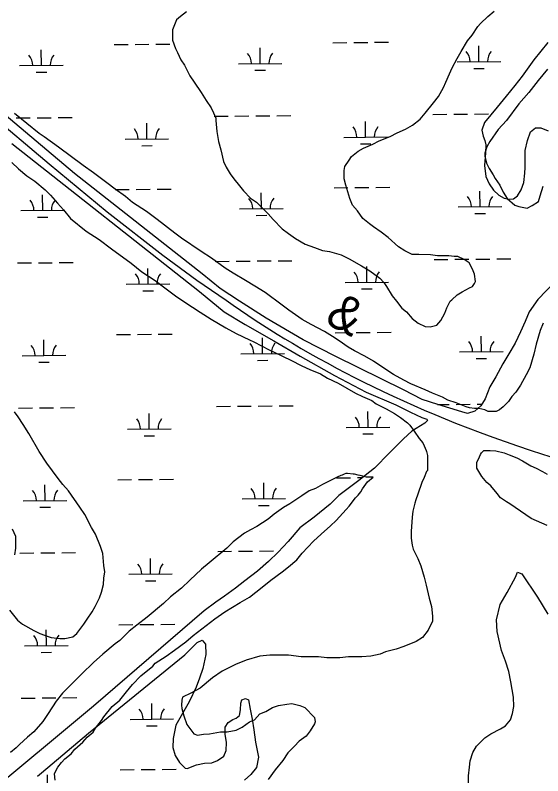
# Model space of a CAD drawing. Extents: x 3568792 to 3606828, y 529143 to 554785.
# Drawn here: x 3581727 to 3582938, y 542432 to 544177 of the extents above; entities that cross this region are included whole.
import ezdxf

# ---------------------------------------------------------------- set-up
doc = ezdxf.new("R2010")
doc.units = 0
for name, color, linetype in [('V-RAIL-IDEN', 7, 'Continuous'), ('V-RAIL-TRAK', 7, 'Continuous'), ('V-SITE-VEGE', 7, 'Continuous'), ('V-WETL-SWMP', 7, 'Continuous')]:
    doc.layers.add(name, color=color, linetype=linetype)

msp = doc.modelspace()

# ---------------------------------------------------------------- linework, layer by layer
at = {"layer": 'V-RAIL-TRAK'}
for points in [[(3580851.8, 544633.4), (3580996.5, 544512.4), (3581029.1, 544485.4), (3581051.8, 544466.2), (3581134, 544398.3), (3581292.9, 544265), (3581431.3, 544149.1), (3581532, 544064.7), (3581661.7, 543956.6), (3581805.1, 543836.1), (3581938.4, 543725.6), (3582066.2, 543626.6), (3582144.1, 543569.4), (3582211.4, 543523.5)], [(3582211.4, 543523.5), (3582227.8, 543511.8), (3582244.3, 543500.2), (3582260.9, 543488.8), (3582277.7, 543477.6), (3582294.6, 543466.6), (3582311.6, 543455.8), (3582328.8, 543445.2), (3582346, 543434.7), (3582363.4, 543424.5), (3582383.5, 543412.7), (3582403.7, 543401.2), (3582424, 543389.8), (3582444.5, 543378.6), (3582465, 543367.5), (3582485.6, 543356.7), (3582506.3, 543346.1), (3582527.1, 543335.6), (3582548, 543325.3), (3582571.4, 543314.1), (3582595, 543303.1), (3582618.6, 543292.3), (3582642.3, 543281.7), (3582666.1, 543271.2), (3582690, 543260.9), (3582713.9, 543250.9), (3582737.9, 543241), (3582766.2, 543230.2), (3582794.6, 543219.6), (3582823, 543209.2), (3582851.5, 543199.1), (3582880.1, 543189.2), (3582908.8, 543179.4), (3582937.5, 543169.9), (3582966.3, 543160.6)]]:
    msp.add_lwpolyline(points, dxfattribs=at)
at = {"layer": 'V-SITE-VEGE'}
for points in [[(3582120.1, 544184.3), (3582106.6, 544174.1), (3582097.5, 544166.1), (3582088.4, 544143.5), (3582088.4, 544119.7), (3582095.2, 544100.5), (3582099.7, 544091.4), (3582107.7, 544074.4), (3582115.6, 544062), (3582128, 544038.2), (3582138.2, 544023.5), (3582154.1, 543999.7), (3582165.4, 543981.6)], [(3582794.9, 544158.1), (3582811.9, 544174), (3582826.7, 544186.4)], [(3582165.4, 543981.6), (3582176.7, 543964.6), (3582182.4, 543953.3), (3582188, 543940.8), (3582188, 543935.2), (3582190.3, 543910.2), (3582193.7, 543887.6), (3582199.4, 543868.4), (3582205, 543841.2), (3582211.8, 543828.7), (3582220.9, 543812.9), (3582228.8, 543801.5), (3582242.4, 543785.7), (3582251.4, 543774.4), (3582267.3, 543757.4), (3582280.9, 543748.3), (3582308, 543721.1), (3582319.4, 543708.7), (3582339.7, 543687.2), (3582354.4, 543675.9), (3582370.3, 543664.5), (3582392.9, 543652.1), (3582414.5, 543644.1), (3582432.6, 543637.3), (3582448.4, 543635.1), (3582475.6, 543627.2), (3582493.7, 543618.1), (3582522, 543602.2), (3582541.3, 543590.9), (3582563.9, 543573.9), (3582573, 543563.7), (3582579.7, 543554.7), (3582592.2, 543533.2), (3582602.4, 543520.7), (3582614.8, 543504.9), (3582625, 543496.9), (3582638.6, 543481.1), (3582652.2, 543470.9), (3582668, 543463), (3582679.4, 543461.8), (3582695.2, 543466.3), (3582704.3, 543476.5), (3582713.3, 543493.5), (3582717.9, 543506), (3582725.8, 543520.7), (3582729.2, 543524.1), (3582741.7, 543535.4), (3582753, 543542.2), (3582770, 543551.3), (3582776.8, 543554.7), (3582781.3, 543561.4), (3582783.5, 543566), (3582781.3, 543583), (3582776.8, 543594.3), (3582768.8, 543609), (3582757.5, 543616.9), (3582742.8, 543623.7), (3582734.9, 543623.7), (3582722.4, 543624.9), (3582696.4, 543624.9), (3582680.5, 543627.1), (3582653.3, 543628.3), (3582638.6, 543628.3), (3582621.6, 543636.2), (3582606.9, 543645.3), (3582583.2, 543666.8), (3582567.3, 543679.2), (3582549.2, 543691.7), (3582540.1, 543698.5), (3582525.4, 543710.9), (3582513, 543727.9), (3582501.6, 543741.5), (3582494.9, 543756.2), (3582485.8, 543786.8), (3582482.4, 543801.5), (3582482.4, 543820.8), (3582483.5, 543829.8), (3582493.7, 543844.5), (3582499.4, 543852.5), (3582514.1, 543864.9), (3582526.6, 543871.7), (3582548.1, 543880.8), (3582562.8, 543888.7), (3582587.7, 543898.9), (3582603.6, 543906.8), (3582622.8, 543915.9), (3582638.7, 543924.9), (3582656.8, 543938.5), (3582668.1, 543952.1), (3582687.4, 543975.9), (3582698.7, 543990.6), (3582710, 544010.9), (3582715.7, 544023.4), (3582723.6, 544042.7), (3582730.4, 544056.2), (3582741.7, 544077.7), (3582750.8, 544093.6), (3582765.5, 544118.5), (3582775.7, 544131), (3582789.3, 544151.3), (3582794.9, 544158.1)], [(3582948.9, 544052.8), (3582927.4, 544026.8), (3582905.9, 543999.6), (3582883.2, 543973.6), (3582854.9, 543935.1), (3582835.7, 543914.7), (3582816.4, 543887.5), (3582809.6, 543875.1), (3582805.1, 543860.4), (3582805.1, 543853.6), (3582808.5, 543837.7), (3582815.3, 543825.2), (3582824.3, 543810.5), (3582828.9, 543802.6), (3582839.1, 543786.8), (3582847, 543770.9), (3582856, 543756.2), (3582874.1, 543741.5), (3582883.2, 543738.1), (3582902.5, 543734.7), (3582913.8, 543740.3), (3582928.5, 543749.4), (3582931.9, 543763), (3582938.7, 543784.5)], [(3582781.2, 543275), (3582769.9, 543276.1), (3582762, 543278.4), (3582739.4, 543287.5), (3582720.1, 543294.2), (3582707.7, 543301), (3582685, 543310.1), (3582668, 543318), (3582635.2, 543331.6), (3582619.3, 543339.6), (3582595.6, 543353.1), (3582577.5, 543364.5), (3582549.2, 543383.7), (3582529.9, 543395), (3582506.1, 543407.5), (3582491.4, 543415.4), (3582471, 543430.1), (3582455.2, 543440.3), (3582437.1, 543451.7), (3582406.5, 543467.5), (3582386.1, 543478.8), (3582355.6, 543500.4), (3582339.7, 543511.7), (3582301.2, 543541.1), (3582277.4, 543555.8), (3582255.9, 543568.3), (3582227.6, 543585.3), (3582209.5, 543596.6), (3582177.8, 543619.3), (3582154, 543635.1), (3582108.8, 543665.7), (3582094, 543677), (3582053.3, 543708.7), (3582028.4, 543726.8), (3581996.7, 543747.2), (3581980.8, 543760.8), (3581957.1, 543777.8), (3581937.8, 543792.5), (3581907.2, 543815.2), (3581883.5, 543832.2), (3581826.9, 543874.1), (3581794, 543897.8), (3581782.7, 543905.8), (3581726.1, 543951.1)], [(3581719.3, 543839), (3581735.1, 543824.3), (3581754.4, 543808.4), (3581772.5, 543795.9), (3581796.3, 543776.7), (3581808.7, 543764.2), (3581824.6, 543746.1), (3581838.2, 543730.3), (3581854, 543711), (3581890.2, 543681.6), (3581919.7, 543662.3), (3581948, 543640.8), (3581993.3, 543608), (3582018.2, 543588.7), (3582048.7, 543568.3), (3582068, 543553.6), (3582095.1, 543533.2), (3582116.7, 543518.5), (3582151.8, 543495.9), (3582176.7, 543480), (3582210.6, 543459.6), (3582234.4, 543447.2), (3582265, 543432.4), (3582275.2, 543427.9), (3582310.3, 543409.8), (3582318.2, 543405.3), (3582342, 543393.9), (3582360.1, 543386), (3582385, 543372.4), (3582403.1, 543364.5), (3582428, 543354.3), (3582443.9, 543344.1), (3582468.8, 543332.8), (3582508.4, 543310.1), (3582524.2, 543302.2), (3582545.7, 543293.1), (3582555.9, 543285.2), (3582578.6, 543273.9), (3582597.8, 543263.7), (3582611.4, 543254.6), (3582627.3, 543242.2), (3582632.9, 543236.5), (3582643.1, 543222.9), (3582654.4, 543205.9), (3582662.4, 543195.8), (3582665.8, 543189), (3582670.3, 543178.8), (3582671.4, 543176.5), (3582673.7, 543167.4), (3582673.7, 543132.3), (3582671.4, 543130.1), (3582665.7, 543116.5), (3582660.1, 543105.2), (3582651, 543078), (3582646.5, 543065.5), (3582644.2, 543057.6), (3582639.7, 543039.5), (3582638.6, 543025.9), (3582636.3, 542993.1), (3582636.3, 542977.2), (3582638.5, 542961.4), (3582640.8, 542952.3), (3582651, 542930.8), (3582657.8, 542913.8), (3582665.7, 542887.8), (3582670.2, 542869.7), (3582677, 542840.2), (3582682.7, 542821), (3582685, 542798.3), (3582684.9, 542787), (3582674.8, 542766.6), (3582662.3, 542749.7), (3582647.6, 542740.6), (3582619.3, 542729.3), (3582601.2, 542722.5), (3582577.4, 542716.8), (3582564.9, 542711.2), (3582543.4, 542706.6), (3582523, 542705.5), (3582492.5, 542705.5), (3582472.1, 542703.3)], [(3582938.6, 543470.8), (3582931.9, 543453.9), (3582922.8, 543422.2), (3582917.1, 543399.5), (3582908.1, 543367.8), (3582900.1, 543352), (3582886.6, 543328.2), (3582876.4, 543312.3), (3582867.3, 543302.2), (3582859.4, 543290.8), (3582846.9, 543278.4), (3582839, 543271.6), (3582831.1, 543268.2), (3582813, 543268.2), (3582805, 543271.6), (3582791.4, 543275), (3582781.2, 543275)], [(3581714.6, 542812), (3581732.7, 542789.4), (3581744.1, 542780.3), (3581770.1, 542765.6), (3581783.7, 542758.8), (3581805.2, 542750.9), (3581809.7, 542749.8), (3581830.1, 542747.5), (3581841.4, 542747.5), (3581859.6, 542750.9), (3581868.6, 542758.8), (3581884.5, 542780.3), (3581892.4, 542791.6), (3581903.7, 542808.6), (3581910.5, 542821.1), (3581920.7, 542840.3), (3581925.2, 542853.9), (3581929.8, 542870.9), (3581930.9, 542885.6), (3581933.2, 542900.3), (3581930.9, 542915.1), (3581928.6, 542942.2), (3581923, 542958.1), (3581911.7, 542986.4), (3581902.6, 543002.2), (3581886.8, 543031.7), (3581875.4, 543048.7), (3581849.4, 543086), (3581837, 543100.7), (3581825.6, 543114.3), (3581799.6, 543149.4), (3581782.6, 543176.6), (3581758.8, 543217.4), (3581745.3, 543237.8), (3581733.9, 543255.9), (3581726, 543267.2)], [(3582947.7, 543006.6), (3582911.4, 543022.5), (3582886.5, 543039.5), (3582862.7, 543056.5), (3582854.8, 543061), (3582841.2, 543070.1), (3582833.3, 543080.2), (3582818.6, 543097.2), (3582809.5, 543105.2), (3582798.2, 543118.7), (3582793.7, 543126.7), (3582786.9, 543138), (3582786.9, 543151.6), (3582790.3, 543158.4), (3582794.8, 543169.7), (3582797.1, 543173.1), (3582802.7, 543178.8), (3582817.5, 543178.7), (3582829.9, 543177.6), (3582849.2, 543173.1), (3582860.5, 543168.6), (3582878.6, 543161.8), (3582891.1, 543155), (3582910.3, 543143.6), (3582922.8, 543138), (3582937.5, 543130.1), (3582947.7, 543124.4)], [(3582339.6, 542900.3), (3582354.4, 542911.6), (3582373.6, 542927.4), (3582386.1, 542943.3), (3582412.1, 542970.5), (3582429.1, 542986.3), (3582450.6, 543005.6), (3582464.2, 543018), (3582486.8, 543042.9), (3582493.6, 543050.8), (3582508.4, 543070.1), (3582514, 543075.8), (3582520.8, 543083.7), (3582524.2, 543090.5), (3582535.5, 543106.3), (3582549.1, 543117.6), (3582533.3, 543117.6), (3582518.6, 543121), (3582514, 543122.2), (3582506.1, 543124.4), (3582502.7, 543124.4), (3582490.2, 543125.6), (3582485.7, 543125.6), (3582482.3, 543124.4), (3582477.8, 543122.2), (3582474.4, 543121), (3582466.5, 543117.7), (3582445, 543106.3), (3582432.5, 543100.7), (3582416.6, 543091.6), (3582401.9, 543086), (3582384.9, 543074.6), (3582373.6, 543066.7), (3582357.8, 543056.5), (3582343, 543047.5), (3582321.5, 543032.8), (3582307.9, 543021.4), (3582281.9, 543004.5), (3582267.2, 542996.5), (3582253.6, 542988.6), (3582227.6, 542969.4), (3582212.8, 542954.6), (3582172.1, 542920.7), (3582155.1, 542906), (3582127.9, 542881.1), (3582108.7, 542862.9), (3582083.7, 542842.6), (3582067.9, 542827.9), (3582030.5, 542796.2), (3582006.7, 542778), (3581988.6, 542764.5), (3581967.1, 542742.9), (3581956.9, 542735), (3581928.6, 542711.2), (3581907.1, 542692), (3581879.9, 542666), (3581835.8, 542621.8), (3581821, 542603.7), (3581802.9, 542575.4), (3581790.5, 542557.3), (3581770.1, 542533.5), (3581755.4, 542521.1), (3581737.2, 542504.1), (3581729.3, 542496.2), (3581716.9, 542486)], [(3581720.3, 542998.9), (3581728.2, 542981.9), (3581728.2, 542954.7), (3581726, 542938.9)], [(3581818.8, 542422.5), (3581817.6, 542437.3), (3581821, 542445.2), (3581825.5, 542452), (3581833.5, 542463.3), (3581841.4, 542471.2), (3581856.1, 542482.6), (3581864, 542493.9), (3581882.2, 542509.7), (3581892.4, 542521), (3581905.9, 542532.4), (3581911.6, 542541.4), (3581925.2, 542559.5), (3581930.9, 542567.5), (3581950.1, 542591.2), (3581967.1, 542605.9), (3581982.9, 542625.2), (3581996.5, 542642.2), (3582015.8, 542661.4), (3582043, 542684.1), (3582048.6, 542690.9), (3582073.5, 542706.7), (3582092.8, 542720.3), (3582118.8, 542739.5), (3582135.8, 542754.2), (3582165.3, 542776.9), (3582185.6, 542792.7), (3582208.3, 542808.6), (3582243.4, 542830.1), (3582264.9, 542842.5), (3582294.3, 542865.2), (3582313.6, 542881), (3582339.6, 542900.3)], [(3582767.6, 542396.4), (3582767.6, 542432.6), (3582769.8, 542451.9), (3582771, 542466.6), (3582777.8, 542485.8), (3582785.7, 542500.6), (3582804.9, 542519.8), (3582818.5, 542528.9), (3582841.2, 542540.2), (3582852.5, 542547), (3582863.8, 542560.5), (3582868.3, 542575.3), (3582871.7, 542591.1), (3582870.6, 542612.6), (3582865, 542647.7), (3582860.4, 542671.5), (3582852.5, 542695.3), (3582843.5, 542720.2), (3582833.3, 542763.2), (3582832.1, 542790.4), (3582840.1, 542825.5), (3582855.9, 542852.7), (3582875.2, 542887.8), (3582879.7, 542899.1), (3582889.9, 542895.7), (3582926.1, 542842.5), (3582949.9, 542802.8)], [(3582472.1, 542703.3), (3582442.6, 542703.3), (3582423.4, 542705.5), (3582383.8, 542705.5), (3582354.3, 542708.9), (3582311.3, 542708.9), (3582288.7, 542706.7), (3582257, 542697.6), (3582233.2, 542687.4), (3582202.6, 542672.7), (3582180, 542656.9), (3582151.7, 542633.1), (3582130.1, 542621.8), (3582110.9, 542612.7), (3582109.8, 542605.9), (3582108.6, 542594.6), (3582109.8, 542586.7), (3582114.3, 542569.7), (3582121.1, 542550.4), (3582136.9, 542528.9), (3582146, 542525.5), (3582159.6, 542527.8), (3582173.2, 542528.9), (3582198.1, 542533.5), (3582213.9, 542533.5), (3582234.3, 542536.8), (3582247.9, 542543.6), (3582264.9, 542556.1), (3582276.2, 542560.6), (3582288.6, 542574.2), (3582302.2, 542579.9), (3582318.1, 542588.9), (3582331.7, 542593.4), (3582350.9, 542596.8), (3582362.2, 542598), (3582380.4, 542593.4), (3582391.7, 542588.9), (3582414.3, 542566.3), (3582415.5, 542556.1), (3582414.3, 542551.5), (3582404.1, 542535.7), (3582395.1, 542523.2), (3582379.2, 542511.9), (3582367.9, 542500.6), (3582353.2, 542484.8), (3582341.8, 542467.8), (3582323.7, 542446.3), (3582307.9, 542423.6)]]:
    msp.add_lwpolyline(points, dxfattribs=at)
at = {"layer": 'V-WETL-SWMP'}
for p, q in [((3581954.3, 544109.7), (3581986.3, 544109.9)), ((3582002.3, 544110.1), (3582034.3, 544110.3)), ((3582050.3, 544110.5), (3582082.3, 544110.7)), ((3582456.2, 544113.9), (3582488.2, 544114.2)), ((3582504.2, 544114.3), (3582536.2, 544114.6)), ((3582552.2, 544114.7), (3582584.2, 544115)), ((3581787.6, 544061.8), (3581787.3, 544097.8)), ((3582289.5, 544066), (3582289.2, 544102)), ((3582791.4, 544070.3), (3582791.1, 544106.3)), ((3581737.6, 544061.4), (3581837.6, 544062.2)), ((3582239.5, 544065.6), (3582339.5, 544066.5)), ((3582741.4, 544069.9), (3582841.4, 544070.7)), ((3581775.7, 544046.3), (3581799.7, 544046.5)), ((3582277.6, 544050.5), (3582301.6, 544050.7)), ((3582779.5, 544054.8), (3582803.5, 544055)), ((3581729.8, 543941.3), (3581761.8, 543941.5)), ((3581777.8, 543941.7), (3581809.8, 543941.9)), ((3581825.8, 543942.1), (3581857.8, 543942.3)), ((3582183.7, 543945.1), (3582215.7, 543945.3)), ((3582231.7, 543945.5), (3582263.7, 543945.8)), ((3582279.7, 543945.9), (3582311.7, 543946.2)), ((3582327.7, 543946.3), (3582359.7, 543946.6)), ((3582685.6, 543949.3), (3582717.6, 543949.6)), ((3582733.6, 543949.7), (3582765.6, 543950)), ((3582781.6, 543950.1), (3582813.6, 543950.4)), ((3582029.5, 543893), (3582029.2, 543929)), ((3582531.4, 543897.3), (3582531.1, 543933.3)), ((3581979.5, 543892.6), (3582079.5, 543893.5)), ((3582481.4, 543896.8), (3582581.4, 543897.7)), ((3582017.6, 543877.5), (3582041.6, 543877.7)), ((3582519.5, 543881.7), (3582543.5, 543881.9)), ((3582005.1, 543777.4), (3582037.1, 543777.7)), ((3582053.1, 543777.8), (3582085.1, 543778.1)), ((3582459, 543781.2), (3582491, 543781.5)), ((3582507, 543781.6), (3582539, 543781.9)), ((3582555, 543782), (3582587, 543782.3)), ((3581790.4, 543729.1), (3581790.1, 543765.1)), ((3581957.1, 543777), (3581989.1, 543777.3)), ((3582292.3, 543733.4), (3582292, 543769.4)), ((3582794.2, 543737.6), (3582793.9, 543773.6)), ((3581740.4, 543728.7), (3581840.4, 543729.5)), ((3582242.3, 543733), (3582342.3, 543733.8)), ((3582744.2, 543737.2), (3582844.2, 543738)), ((3581778.5, 543713.6), (3581802.5, 543713.8)), ((3582280.4, 543717.9), (3582304.4, 543718.1)), ((3582782.3, 543722.1), (3582806.3, 543722.3)), ((3581732.5, 543608.6), (3581764.5, 543608.8)), ((3581780.5, 543609), (3581812.5, 543609.2)), ((3581828.5, 543609.4), (3581860.5, 543609.6)), ((3582186.5, 543612.4), (3582218.5, 543612.7)), ((3582234.5, 543612.8), (3582266.5, 543613.1)), ((3582282.5, 543613.2), (3582314.5, 543613.5)), ((3582330.5, 543613.6), (3582362.5, 543613.9)), ((3582688.4, 543616.7), (3582720.4, 543616.9)), ((3582736.4, 543617.1), (3582768.4, 543617.3)), ((3582784.4, 543617.5), (3582816.4, 543617.7)), ((3582832.4, 543617.9), (3582864.4, 543618.1)), ((3582032.3, 543560.3), (3582032, 543596.3)), ((3582534.2, 543564.6), (3582533.9, 543600.6)), ((3581982.3, 543559.9), (3582082.3, 543560.8)), ((3582484.2, 543564.2), (3582584.2, 543565)), ((3582020.4, 543544.8), (3582044.4, 543545)), ((3582522.3, 543549.1), (3582546.3, 543549.3)), ((3582461.8, 543448.6), (3582493.8, 543448.8)), ((3582509.8, 543449), (3582541.8, 543449.2)), ((3582557.8, 543449.4), (3582589.8, 543449.6)), ((3581793.2, 543396.5), (3581792.9, 543432.5)), ((3581959.8, 543444.3), (3581991.8, 543444.6)), ((3582007.8, 543444.7), (3582039.8, 543445)), ((3582055.8, 543445.1), (3582087.8, 543445.4)), ((3582295.1, 543400.7), (3582294.8, 543436.7)), ((3582797, 543405), (3582796.7, 543441)), ((3581743.2, 543396), (3581843.2, 543396.9)), ((3582245.1, 543400.3), (3582345.1, 543401.1)), ((3582747, 543404.5), (3582847, 543405.4)), ((3581781.3, 543380.9), (3581805.3, 543381.1)), ((3582283.2, 543385.2), (3582307.2, 543385.4)), ((3582785.1, 543389.4), (3582809.1, 543389.6)), ((3581735.3, 543275.9), (3581767.3, 543276.2)), ((3581783.3, 543276.3), (3581815.3, 543276.6)), ((3581831.3, 543276.7), (3581863.3, 543277)), ((3582189.2, 543279.7), (3582221.2, 543280)), ((3582237.2, 543280.1), (3582269.2, 543280.4)), ((3582285.2, 543280.5), (3582317.2, 543280.8)), ((3582333.2, 543280.9), (3582365.2, 543281.2)), ((3582696.1, 543284), (3582723.2, 543284.3)), ((3582739.2, 543284.4), (3582771.2, 543284.7)), ((3582787.2, 543284.8), (3582798.3, 543284.9)), ((3582035.1, 543227.7), (3582034.8, 543263.7)), ((3582537, 543231.9), (3582536.7, 543267.9)), ((3581985.1, 543227.3), (3582085.1, 543228.1)), ((3582487, 543231.5), (3582587, 543232.3)), ((3582023.2, 543212.2), (3582047.2, 543212.4)), ((3582525.1, 543216.4), (3582549.1, 543216.6)), ((3582464.5, 543115.9), (3582496.5, 543116.1)), ((3582512.5, 543116.3), (3582524.2, 543116.4)), ((3581796, 543063.8), (3581795.7, 543099.8)), ((3581962.6, 543111.6), (3581994.6, 543111.9)), ((3582010.6, 543112), (3582042.6, 543112.3)), ((3582058.6, 543112.4), (3582090.6, 543112.7)), ((3582297.9, 543068), (3582297.6, 543104)), ((3581746, 543063.4), (3581846, 543064.2)), ((3582247.9, 543067.6), (3582347.9, 543068.5)), ((3581784.1, 543048.3), (3581808.1, 543048.5)), ((3582286, 543052.5), (3582310, 543052.7)), ((3581738.1, 542943.2), (3581770.1, 542943.5)), ((3581786.1, 542943.6), (3581818.1, 542943.9)), ((3581834.1, 542944), (3581866.1, 542944.3)), ((3582192, 542947.1), (3582224, 542947.3)), ((3582240, 542947.5), (3582272, 542947.7)), ((3582288, 542947.9), (3582320, 542948.1)), ((3582037.9, 542895), (3582037.6, 542931)), ((3581987.9, 542894.6), (3582087.9, 542895.4)), ((3582026, 542879.5), (3582050, 542879.7)), ((3581798.8, 542731.1), (3581798.5, 542767.1)), ((3581965.4, 542779), (3581997.4, 542779.2)), ((3582013.4, 542779.4), (3582045.4, 542779.6)), ((3582061.4, 542779.8), (3582093.4, 542780.1)), ((3581748.8, 542730.7), (3581848.8, 542731.6)), ((3581786.9, 542715.6), (3581810.9, 542715.8)), ((3581740.9, 542610.6), (3581772.9, 542610.8)), ((3581788.9, 542611), (3581820.9, 542611.2)), ((3581836.9, 542611.4), (3581868.9, 542611.7)), ((3582040.9, 542562.4), (3582040.6, 542598.4)), ((3581990.9, 542561.9), (3582090.9, 542562.8)), ((3582029, 542546.8), (3582053, 542547)), ((3581801.8, 542398.5), (3581801.5, 542434.5)), ((3581968.5, 542446.3), (3582000.4, 542446.6)), ((3582016.4, 542446.7), (3582048.4, 542447)), ((3582064.4, 542447.1), (3582096.4, 542447.4))]:
    msp.add_line(p, q, dxfattribs=at)
for points in [[(3582949.4, 544114.3), (3582917.7, 544074.4), (3582890.9, 544037.3), (3582873.7, 544015.9), (3582853.6, 543991), (3582833.4, 543965.7), (3582804.2, 543931.2), (3582798.4, 543913.5), (3582801.2, 543899.6), (3582805.4, 543889.7), (3582807.7, 543879.3), (3582806.4, 543861.5), (3582804, 543832.4), (3582807.5, 543807.2), (3582814.6, 543789.8), (3582824.7, 543775.3), (3582836.9, 543764.2), (3582849.1, 543757.1), (3582861.9, 543754.9), (3582870.8, 543755.8), (3582880.3, 543763), (3582888.4, 543776.2), (3582894.2, 543792.9), (3582897, 543814.6), (3582897.2, 543827.9), (3582897.4, 543841.2), (3582897.9, 543866.4), (3582902.7, 543889.5), (3582909.9, 543909.6), (3582921, 543918.3), (3582933.3, 543918.6), (3582950, 543911.9)], [(3582966.4, 543566.5), (3582926.7, 543525.2), (3582906.9, 543496.4), (3582897.2, 543474.4), (3582886.9, 543450.4), (3582874.6, 543424.4), (3582860.4, 543400), (3582846.6, 543377), (3582829.9, 543347.2), (3582816.6, 543324.7), (3582805.8, 543297.2), (3582795.7, 543280.6), (3582782.1, 543268.5), (3582765.2, 543263.3), (3582752.5, 543267), (3582697, 543283.7), (3582661.1, 543295.7), (3582618.5, 543317.7), (3582567.1, 543343.2), (3582463.3, 543394.3), (3582387.9, 543432.1), (3582303.4, 543482.4), (3582242.3, 543521), (3582197.9, 543550.4), (3582156.5, 543583.7), (3581863.6, 543813.8), (3581637.7, 544003.3)], [(3581719.3, 543882.9), (3582150.1, 543543), (3582207, 543496.7), (3582254.8, 543467.8), (3582320.6, 543430.3), (3582381.1, 543394.8), (3582460.1, 543350.6), (3582532.9, 543312.4), (3582600.8, 543283.2), (3582634.1, 543266.4), (3582660.4, 543254.1), (3582672.2, 543250.5), (3582673.6, 543247.5), (3582667.6, 543241.2), (3582637.8, 543223), (3582618.2, 543205.1), (3582586.2, 543173.1), (3582552.1, 543137.7), (3582515.7, 543109.8), (3582494.2, 543093.9), (3582470.3, 543075.6), (3582450.2, 543055.7), (3582413.3, 543025.8), (3582380.8, 543000.8), (3582353.7, 542969.7), (3582330.7, 542945), (3582308.6, 542923.7), (3582283.6, 542901.4), (3582254.2, 542879.8), (3582232.7, 542862.9), (3582207.3, 542844.6), (3582187.9, 542830.7), (3582160.9, 542810.9), (3581906.7, 542591.9), (3581649.8, 542378.7)], [(3581778.3, 542431.7), (3581787.4, 542439), (3581895.8, 542530.1), (3582116.3, 542709.5), (3582144.6, 542737.8), (3582156.4, 542743.2), (3582163.7, 542734.1), (3582164.6, 542710.4), (3582158.2, 542678.5), (3582150, 542656.7), (3582142.7, 542635.7), (3582126.3, 542602), (3582096.2, 542548.3), (3582089.9, 542518.2), (3582088.9, 542497.2), (3582094.4, 542479), (3582104.4, 542462.6), (3582117.2, 542449.9), (3582121.7, 542449), (3582143.1, 542457.5), (3582161.4, 542461.1), (3582178.6, 542462.3), (3582191.5, 542467.5), (3582206, 542477.6), (3582211.6, 542490.3), (3582212, 542509), (3582208.8, 542528.3), (3582209.1, 542543.6), (3582216.2, 542554.3), (3582227.1, 542561.5), (3582234.6, 542564.9), (3582242.1, 542571.1), (3582244.3, 542583.4), (3582245, 542598.7), (3582247.1, 542606.5), (3582255.6, 542609.8), (3582262.4, 542606.3), (3582266.5, 542585.5), (3582271, 542562.3), (3582275.1, 542538), (3582279, 542509.9), (3582285.3, 542475.3), (3582281, 542451.2), (3582267.9, 542435.6), (3582253.9, 542422.1)]]:
    msp.add_lwpolyline(points, dxfattribs=at)
for centre, start, end in [((3582736.1, 544070.3), 359.7115, 41.2552), ((3582846.6, 544071.2), 139.7115, 181.2552), ((3581732.4, 544061.8), 359.7115, 41.2552), ((3581842.8, 544062.8), 139.7115, 181.2552), ((3582234.2, 544066.1), 359.7115, 41.2552), ((3582344.7, 544067), 139.7115, 181.2552), ((3582476.2, 543897.3), 359.7115, 41.2552), ((3582586.6, 543898.2), 139.7115, 181.2552), ((3581974.3, 543893), 359.7115, 41.2552), ((3582084.7, 543894), 139.7115, 181.2552), ((3582738.9, 543737.6), 359.7115, 41.2552), ((3582849.4, 543738.6), 139.7115, 181.2552), ((3581735.1, 543729.1), 359.7115, 41.2552), ((3581845.6, 543730.1), 139.7115, 181.2552), ((3582237.1, 543733.4), 359.7115, 41.2552), ((3582347.5, 543734.3), 139.7115, 181.2552), ((3582479, 543564.6), 359.7115, 41.2552), ((3582589.4, 543565.5), 139.7115, 181.2552), ((3581977, 543560.4), 359.7115, 41.2552), ((3582087.5, 543561.3), 139.7115, 181.2552), ((3581737.9, 543396.5), 359.7115, 41.2552), ((3581848.4, 543397.4), 139.7115, 181.2552), ((3582239.8, 543400.7), 359.7115, 41.2552), ((3582350.3, 543401.6), 139.7115, 181.2552), ((3582741.8, 543405), 359.7115, 41.2552), ((3582852.2, 543405.9), 139.7115, 181.2552), ((3582481.7, 543231.9), 359.7115, 41.2552), ((3582592.2, 543232.9), 139.7115, 181.2552), ((3581979.8, 543227.7), 359.7115, 41.2552), ((3582090.3, 543228.6), 139.7115, 181.2552), ((3581740.7, 543063.8), 359.7115, 41.2552), ((3581851.2, 543064.7), 139.7115, 181.2552), ((3582242.6, 543068), 359.7115, 41.2552), ((3582353.1, 543069), 139.7115, 181.2552), ((3581982.6, 542895), 359.7115, 41.2552), ((3582093.1, 542896), 139.7115, 181.2552), ((3581743.5, 542731.1), 359.7115, 41.2552), ((3581854, 542732.1), 139.7115, 181.2552), ((3581985.6, 542562.4), 359.7115, 41.2552), ((3582096.1, 542563.3), 139.7115, 181.2552)]:
    msp.add_arc(centre, 35.2, start, end, dxfattribs=at)

# ---------------------------------------------------------------- texts
at = {"layer": 'V-RAIL-IDEN'}
msp.add_text('&', height=83, rotation=332.8186, dxfattribs=at).set_placement((3582435.1, 543471.9))

doc.saveas('drawing.dxf')
